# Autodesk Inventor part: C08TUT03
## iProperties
Created: 2009-04
Part Number: C08TUT03
Document SubType Name: Modeling
Designer: Sham
Density: 1 g/cm^3
Author: Sham
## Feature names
1. Extrusion1
2. Hole1
3. Fillet1
4. Extrusion3
